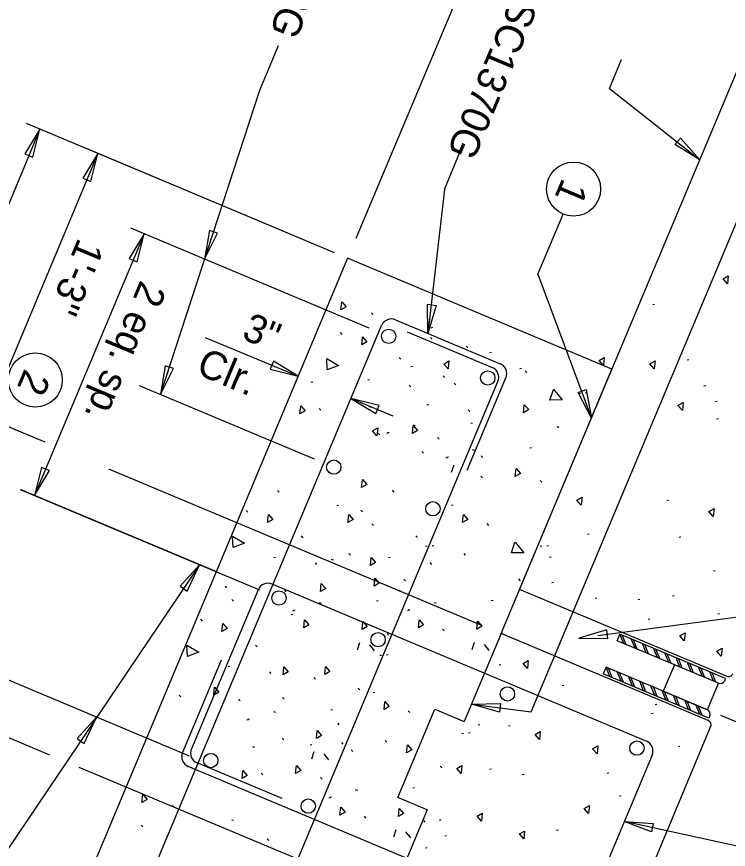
# Model space of a CAD drawing. Extents: x 1968564 to 1968711, y 796599 to 796794.
# Drawn here: x 1968652.64 to 1968665.06, y 796670.24 to 796684.77 of the extents above; entities that cross this region are included whole.
import ezdxf

# ---------------------------------------------------------------- set-up
doc = ezdxf.new("R2010")
doc.units = 0
for name, color, linetype in [('BR_AUTO DIMENSION', 7, 'Continuous'), ('BR_CONCRETE', 7, 'Continuous'), ('BR_DETAILS', 7, 'Continuous'), ('BR_REBAR', 7, 'Continuous'), ('BR_STRUCTURAL STEEL', 7, 'Continuous'), ('BR_TABLE LINES', 7, 'Continuous'), ('BR_TEXT', 7, 'Continuous')]:
    doc.layers.add(name, color=color, linetype=linetype)

msp = doc.modelspace()

# ---------------------------------------------------------------- linework, layer by layer
at = {"layer": 'BR_AUTO DIMENSION'}
for p, q in [((1968664.941, 796696.102), (1968658.562, 796680.894)), ((1968661.621, 796672.639), (1968666.836, 796685.073)), ((1968656.887, 796683.484), (1968657.212, 796684.26)), ((1968662.987, 796683.51), (1968663.2, 796684.017)), ((1968655.153, 796678.177), (1968656.887, 796683.484)), ((1968662.987, 796683.51), (1968664.562, 796682.27)), ((1968657.405, 796680.977), (1968652.818, 796682.901)), ((1968653.049, 796682.804), (1968647.247, 796668.972)), ((1968658.188, 796680.649), (1968653.833, 796682.476)), ((1968654.063, 796682.379), (1968652.129, 796677.768)), ((1968660.108, 796681.751), (1968660.385, 796682.411)), ((1968660.108, 796681.751), (1968659.818, 796679.242)), ((1968661.738, 796680.273), (1968662.179, 796681.323)), ((1968654.869, 796680.979), (1968652.955, 796676.415)), ((1968658.794, 796679.333), (1968654.639, 796681.076)), ((1968661.738, 796680.273), (1968662.672, 796677.764)), ((1968655.936, 796679.172), (1968657.555, 796678.493)), ((1968654.784, 796678.331), (1968657.837, 796677.051)), ((1968659.215, 796677.796), (1968658.477, 796678.106)), ((1968652.903, 796677.443), (1968651.899, 796677.865)), ((1968652.903, 796677.443), (1968651.899, 796677.865)), ((1968652.587, 796677.576), (1968653.134, 796677.347)), ((1968654.248, 796676.88), (1968660.753, 796674.151)), ((1968652.708, 796676.519), (1968656.88, 796674.769)), ((1968656.108, 796675.093), (1968652.725, 796676.512)), ((1968655.837, 796675.204), (1968649.435, 796665.731)), ((1968662.785, 796673.971), (1968666.916, 796674.523)), ((1968655.662, 796671.865), (1968651.507, 796673.607)), ((1968660.58, 796672.776), (1968661.621, 796672.639)), ((1968664.926, 796672.582), (1968671.236, 796669.935)), ((1968652.269, 796672.288), (1968653.22, 796671.889)), ((1968653.729, 796671.675), (1968657.933, 796669.912)), ((1968666.9, 796669.924), (1968663.245, 796670.729))]:
    msp.add_line(p, q, dxfattribs=at)
for points in [[(1968652.925, 796682.314), (1968653.049, 796682.804), (1968652.786, 796682.372)], [(1968664.226, 796682.648), (1968664.562, 796682.27), (1968664.13, 796682.533)], [(1968653.939, 796681.889), (1968654.063, 796682.379), (1968653.801, 796681.947)], [(1968654.745, 796680.489), (1968654.869, 796680.979), (1968654.607, 796680.547)], [(1968656.008, 796681.037), (1968655.924, 796680.538), (1968656.151, 796680.99)], [(1968659.963, 796679.727), (1968659.818, 796679.242), (1968659.815, 796679.748)], [(1968655.237, 796678.676), (1968655.153, 796678.178), (1968655.38, 796678.63)], [(1968657.065, 796678.617), (1968657.555, 796678.493), (1968657.123, 796678.755)], [(1968662.581, 796678.262), (1968662.672, 796677.764), (1968662.439, 796678.213)], [(1968658.968, 796677.982), (1968658.477, 796678.106), (1968658.909, 796677.843)], [(1968653.079, 796676.905), (1968652.955, 796676.415), (1968653.218, 796676.847)], [(1968655.619, 796674.748), (1968655.837, 796675.204), (1968655.495, 796674.832)], [(1968662.94, 796674.069), (1968662.455, 796673.924), (1968662.961, 796673.92)], [(1968661.066, 796672.636), (1968660.58, 796672.776), (1968661.085, 796672.785)], [(1968653.822, 796672.089), (1968654.04, 796672.545), (1968653.698, 796672.173)], [(1968663.718, 796670.548), (1968663.245, 796670.729), (1968663.75, 796670.695)]]:
    msp.add_lwpolyline(points, close=True, dxfattribs=at)
for centre in [(1968662.361, 796681.758), (1968652.969, 796678.429)]:
    msp.add_circle(centre, 0.472, dxfattribs=at)
at = {"layer": 'BR_CONCRETE'}
for p, q in [((1968661.418, 796674.776), (1968665.511, 796684.533)), ((1968658.419, 796680.552), (1968652.617, 796666.719)), ((1968663.03, 796678.618), (1968658.419, 796680.552)), ((1968661.096, 796674.007), (1968663.03, 796678.618)), ((1968665.03, 796673.261), (1968661.418, 796674.776)), ((1968661.096, 796674.007), (1968660.451, 796672.47)), ((1968664.708, 796672.492), (1968661.096, 796674.007)), ((1968664.752, 796672.383), (1968663.068, 796668.368)), ((1968659.807, 796670.933), (1968659.162, 796669.396))]:
    msp.add_line(p, q, dxfattribs=at)
msp.add_lwpolyline([(1968659.807, 796670.933), (1968659.294, 796671.148), (1968659.939, 796672.685), (1968660.451, 796672.47)], dxfattribs=at)
for centre, start, end in [((1968665.062, 796673.338), 247.246, 337.2565), ((1968664.676, 796672.415), 337.246, 67.246)]:
    msp.add_arc(centre, 0.0833, start, end, dxfattribs=at)
at = {"layer": 'BR_DETAILS'}
for p, q in [((1968663.745, 796679.746), (1968663.774, 796679.752)), ((1968658.838, 796679.601), (1968658.866, 796679.571)), ((1968658.291, 796679.254), (1968658.319, 796679.224)), ((1968659.902, 796679.341), (1968659.873, 796679.335)), ((1968659.867, 796679.169), (1968659.896, 796679.139)), ((1968660.486, 796679.019), (1968660.514, 796678.989)), ((1968659.321, 796678.822), (1968659.349, 796678.792)), ((1968660.932, 796678.909), (1968660.902, 796678.903)), ((1968659.52, 796678.664), (1968659.549, 796678.67)), ((1968664.344, 796678.779), (1968664.373, 796678.785)), ((1968661.451, 796678.626), (1968661.421, 796678.621)), ((1968661.516, 796678.587), (1968661.544, 796678.558)), ((1968657.812, 796678.382), (1968657.776, 796678.392)), ((1968658.803, 796678.43), (1968658.773, 796678.424)), ((1968660.084, 796678.502), (1968660.112, 796678.472)), ((1968660.28, 796678.375), (1968660.308, 796678.345)), ((1968659.492, 796678.339), (1968659.52, 796678.309)), ((1968664.636, 796678.328), (1968664.666, 796678.334)), ((1968662.481, 796678.195), (1968662.451, 796678.189)), ((1968662.595, 796678.202), (1968662.565, 796678.196)), ((1968657.922, 796677.933), (1968657.95, 796677.903)), ((1968658.842, 796677.95), (1968658.805, 796677.96)), ((1968659.833, 796677.998), (1968659.803, 796677.992)), ((1968664.835, 796678.051), (1968664.864, 796678.057)), ((1968660.522, 796677.907), (1968660.55, 796677.878)), ((1968659.605, 796677.63), (1968659.569, 796677.64)), ((1968660.596, 796677.678), (1968660.567, 796677.672)), ((1968664.855, 796677.75), (1968664.884, 796677.755)), ((1968658.952, 796677.501), (1968658.98, 796677.471)), ((1968659.131, 796677.502), (1968659.101, 796677.497)), ((1968659.146, 796677.514), (1968659.117, 796677.508)), ((1968662.073, 796677.623), (1968662.101, 796677.593)), ((1968659.986, 796677.428), (1968660.014, 796677.398)), ((1968660.635, 796677.198), (1968660.598, 796677.208)), ((1968661.626, 796677.246), (1968661.596, 796677.24)), ((1968659.715, 796677.181), (1968659.743, 796677.151)), ((1968660.161, 796677.07), (1968660.131, 796677.065)), ((1968660.176, 796677.082), (1968660.146, 796677.076)), ((1968660.75, 796677.108), (1968660.778, 796677.078)), ((1968660.234, 796676.823), (1968660.275, 796676.95)), ((1968660.745, 796676.749), (1968660.773, 796676.719)), ((1968661.779, 796676.676), (1968661.808, 796676.646)), ((1968657.196, 796676.502), (1968657.224, 796676.472)), ((1968659.197, 796676.504), (1968659.225, 796676.474)), ((1968663.99, 796676.326), (1968664.02, 796676.332)), ((1968658.26, 796676.242), (1968658.231, 796676.236)), ((1968660.262, 796676.244), (1968660.232, 796676.239)), ((1968656.649, 796676.155), (1968656.677, 796676.125)), ((1968658.651, 796676.157), (1968658.679, 796676.127)), ((1968658.844, 796675.92), (1968658.872, 796675.891)), ((1968660.846, 796675.923), (1968660.874, 796675.893)), ((1968657.608, 796675.708), (1968657.636, 796675.678)), ((1968659.609, 796675.71), (1968659.638, 796675.68)), ((1968662.607, 796675.737), (1968662.636, 796675.743)), ((1968664.201, 796675.686), (1968664.23, 796675.692)), ((1968659.809, 796675.528), (1968659.779, 796675.522)), ((1968659.923, 796675.535), (1968659.894, 796675.529)), ((1968661.81, 796675.53), (1968661.781, 796675.524)), ((1968661.925, 796675.537), (1968661.895, 796675.532)), ((1968657.161, 796675.331), (1968657.131, 796675.325)), ((1968658.442, 796675.403), (1968658.47, 796675.373)), ((1968659.163, 796675.333), (1968659.133, 796675.327)), ((1968660.444, 796675.405), (1968660.472, 796675.375)), ((1968661.941, 796675.339), (1968661.97, 796675.345)), ((1968657.85, 796675.24), (1968657.878, 796675.211)), ((1968658.171, 796675.285), (1968658.135, 796675.296)), ((1968659.852, 796675.243), (1968659.88, 796675.213)), ((1968664.8, 796675.098), (1968664.829, 796675.104)), ((1968659.401, 796674.956), (1968659.429, 796674.926)), ((1968661.403, 796674.958), (1968661.431, 796674.928)), ((1968661.98, 796674.898), (1968662.009, 796674.903)), ((1968656.28, 796674.834), (1968656.308, 796674.804)), ((1968657.315, 796674.761), (1968657.343, 796674.731)), ((1968659.316, 796674.763), (1968659.344, 796674.733)), ((1968656.398, 796674.6), (1968656.426, 796674.571)), ((1968662.736, 796674.622), (1968662.766, 796674.628)), ((1968663.49, 796674.598), (1968663.519, 796674.603)), ((1968664.085, 796674.661), (1968664.114, 796674.667)), ((1968657.963, 796674.531), (1968657.927, 796674.541)), ((1968658.954, 796674.579), (1968658.925, 796674.573)), ((1968659.964, 796674.533), (1968659.928, 796674.544)), ((1968660.956, 796674.581), (1968660.926, 796674.575)), ((1968657.463, 796674.341), (1968657.433, 796674.335)), ((1968657.489, 796674.403), (1968657.459, 796674.398)), ((1968657.504, 796674.415), (1968657.475, 796674.409)), ((1968659.491, 796674.406), (1968659.461, 796674.4)), ((1968659.506, 796674.417), (1968659.476, 796674.412)), ((1968664.876, 796674.35), (1968664.905, 796674.355)), ((1968655.852, 796674.254), (1968655.88, 796674.224)), ((1968663.662, 796674.255), (1968663.691, 796674.261)), ((1968659.108, 796674.009), (1968659.136, 796673.979)), ((1968660.075, 796674.084), (1968660.103, 796674.054)), ((1968661.109, 796674.011), (1968661.137, 796673.981)), ((1968656.81, 796673.806), (1968656.839, 796673.777)), ((1968658.592, 796673.724), (1968658.633, 796673.851)), ((1968658.799, 796673.811), (1968658.883, 796673.707)), ((1968660.594, 796673.726), (1968660.635, 796673.853)), ((1968660.8, 796673.813), (1968660.885, 796673.71)), ((1968659.011, 796673.626), (1968658.982, 796673.621)), ((1968659.126, 796673.634), (1968659.096, 796673.628)), ((1968656.364, 796673.43), (1968656.334, 796673.424)), ((1968661.063, 796673.461), (1968661.092, 796673.467)), ((1968657.053, 796673.339), (1968657.081, 796673.309)), ((1968657.828, 796673.238), (1968657.856, 796673.208)), ((1968658.604, 796673.054), (1968658.632, 796673.025)), ((1968662.161, 796673.102), (1968662.19, 796673.108)), ((1968655.482, 796672.932), (1968655.511, 796672.903)), ((1968656.517, 796672.86), (1968656.545, 796672.83)), ((1968657.281, 796672.892), (1968657.309, 796672.862)), ((1968658.892, 796672.979), (1968658.863, 796672.973)), ((1968663.784, 796672.767), (1968663.814, 796672.772)), ((1968657.165, 796672.63), (1968657.129, 796672.64)), ((1968658.157, 796672.678), (1968658.127, 796672.672)), ((1968659.476, 796672.657), (1968659.504, 796672.627)), ((1968663.72, 796672.613), (1968663.749, 796672.619)), ((1968656.692, 796672.502), (1968656.662, 796672.496)), ((1968656.707, 796672.514), (1968656.677, 796672.508)), ((1968658.24, 796672.444), (1968658.268, 796672.414)), ((1968660.696, 796672.414), (1968660.726, 796672.42)), ((1968660.441, 796672.264), (1968660.411, 796672.258)), ((1968660.555, 796672.272), (1968660.525, 796672.266)), ((1968661.224, 796672.398), (1968661.254, 796672.404)), ((1968657.276, 796672.18), (1968657.304, 796672.151)), ((1968659.074, 796672.139), (1968659.102, 796672.11)), ((1968656.802, 796672.019), (1968656.766, 796672.03)), ((1968657.793, 796672.067), (1968657.763, 796672.062)), ((1968658.31, 796672.108), (1968658.338, 796672.078)), ((1968658.482, 796671.977), (1968658.51, 796671.947)), ((1968664.189, 796672.035), (1968664.218, 796672.04)), ((1968657.795, 796671.823), (1968657.836, 796671.949)), ((1968658.001, 796671.909), (1968658.086, 796671.806)), ((1968660.033, 796671.692), (1968660.061, 796671.662)), ((1968656.912, 796671.57), (1968656.94, 796671.54)), ((1968660.9, 796671.642), (1968660.929, 796671.648)), ((1968661.467, 796671.546), (1968661.497, 796671.551)), ((1968662.947, 796671.571), (1968662.976, 796671.577)), ((1968657.947, 796671.497), (1968657.975, 796671.468)), ((1968658.595, 796671.267), (1968658.559, 796671.278)), ((1968659.586, 796671.315), (1968659.557, 796671.31)), ((1968658.121, 796671.14), (1968658.091, 796671.134)), ((1968658.136, 796671.152), (1968658.107, 796671.146)), ((1968663.16, 796671.175), (1968663.19, 796671.181)), ((1968655.366, 796671.009), (1968655.394, 796670.979)), ((1968658.705, 796670.818), (1968658.733, 796670.788)), ((1968656.43, 796670.75), (1968656.401, 796670.744)), ((1968659.74, 796670.745), (1968659.768, 796670.716)), ((1968660.022, 796670.754), (1968660.052, 796670.76)), ((1968654.819, 796670.662), (1968654.847, 796670.633)), ((1968659.224, 796670.46), (1968659.265, 796670.587)), ((1968659.431, 796670.547), (1968659.515, 796670.444)), ((1968662.066, 796670.579), (1968662.096, 796670.585)), ((1968657.014, 796670.428), (1968657.042, 796670.398)), ((1968660.117, 796670.479), (1968660.146, 796670.485)), ((1968659.779, 796670.269), (1968659.808, 796670.275))]:
    msp.add_line(p, q, dxfattribs=at)
for points in [[(1968665.048, 796680.108), (1968664.971, 796680.195), (1968665.061, 796680.247), (1968665.048, 796680.108)], [(1968658.316, 796679.789), (1968658.393, 796679.703), (1968658.303, 796679.65), (1968658.316, 796679.789)], [(1968658.678, 796679.181), (1968658.755, 796679.095), (1968658.665, 796679.042), (1968658.678, 796679.181)], [(1968658.055, 796678.804), (1968658.262, 796678.681), (1968658.062, 796678.603), (1968658.055, 796678.799)], [(1968662.882, 796678.684), (1968662.806, 796678.77), (1968662.895, 796678.823), (1968662.882, 796678.684)], [(1968660.172, 796678.621), (1968660.095, 796678.707), (1968660.185, 796678.76), (1968660.172, 796678.621)], [(1968663.769, 796678.624), (1968663.692, 796678.71), (1968663.782, 796678.763), (1968663.769, 796678.624)], [(1968662.01, 796678.267), (1968662.163, 796678.081), (1968661.949, 796678.076), (1968662.009, 796678.263)], [(1968657.6, 796677.977), (1968657.677, 796677.891), (1968657.587, 796677.838), (1968657.6, 796677.977)], [(1968661.501, 796677.997), (1968661.578, 796677.911), (1968661.488, 796677.858), (1968661.501, 796677.997)], [(1968664.26, 796677.895), (1968664.183, 796677.982), (1968664.273, 796678.034), (1968664.26, 796677.895)], [(1968658.931, 796677.456), (1968658.854, 796677.543), (1968658.944, 796677.595), (1968658.931, 796677.456)], [(1968659.564, 796677.637), (1968659.64, 796677.55), (1968659.551, 796677.498), (1968659.564, 796677.637)], [(1968661.357, 796676.885), (1968661.434, 796676.798), (1968661.344, 796676.746), (1968661.357, 796676.885)], [(1968658.676, 796676.692), (1968658.752, 796676.606), (1968658.663, 796676.553), (1968658.676, 796676.692)], [(1968662.496, 796676.248), (1968662.419, 796676.334), (1968662.509, 796676.387), (1968662.496, 796676.248)], [(1968664.799, 796676.047), (1968664.723, 796676.134), (1968664.813, 796676.186), (1968664.799, 796676.047)], [(1968657.036, 796676.082), (1968657.113, 796675.996), (1968657.023, 796675.943), (1968657.036, 796676.082)], [(1968658.438, 796676.082), (1968658.515, 796675.995), (1968658.425, 796675.943), (1968658.438, 796676.082)], [(1968660.439, 796676.084), (1968660.516, 796675.998), (1968660.426, 796675.945), (1968660.439, 796676.084)], [(1968656.413, 796675.705), (1968656.62, 796675.582), (1968656.42, 796675.504), (1968656.413, 796675.701)], [(1968661.34, 796675.602), (1968661.493, 796675.416), (1968661.278, 796675.411), (1968661.339, 796675.598)], [(1968658.829, 796675.33), (1968658.906, 796675.244), (1968658.816, 796675.191), (1968658.829, 796675.33)], [(1968657.96, 796674.881), (1968658.037, 796674.794), (1968657.947, 796674.742), (1968657.96, 796674.881)], [(1968658.894, 796674.972), (1968658.97, 796674.886), (1968658.881, 796674.833), (1968658.894, 796674.972)], [(1968656.239, 796674.181), (1968656.315, 796674.095), (1968656.225, 796674.042), (1968656.239, 796674.181)], [(1968657.667, 796674.243), (1968657.743, 796674.157), (1968657.654, 796674.104), (1968657.667, 796674.243)], [(1968658.685, 796674.218), (1968658.762, 796674.131), (1968658.672, 796674.079), (1968658.685, 796674.218)], [(1968659.668, 796674.245), (1968659.745, 796674.159), (1968659.655, 796674.106), (1968659.668, 796674.245)], [(1968660.687, 796674.22), (1968660.763, 796674.134), (1968660.674, 796674.081), (1968660.687, 796674.22)], [(1968664.292, 796673.878), (1968664.216, 796673.964), (1968664.306, 796674.017), (1968664.292, 796673.878)], [(1968655.616, 796673.803), (1968655.823, 796673.681), (1968655.623, 796673.603), (1968655.616, 796673.799)], [(1968664.939, 796673.612), (1968664.863, 796673.698), (1968664.952, 796673.751), (1968664.939, 796673.612)], [(1968657.306, 796673.427), (1968657.383, 796673.34), (1968657.293, 796673.288), (1968657.306, 796673.427)], [(1968658.032, 796673.429), (1968658.108, 796673.342), (1968658.019, 796673.29), (1968658.032, 796673.429)], [(1968661.558, 796673.399), (1968661.481, 796673.485), (1968661.571, 796673.538), (1968661.558, 796673.399)], [(1968656.095, 796673.068), (1968656.171, 796672.982), (1968656.082, 796672.93), (1968656.095, 796673.068)], [(1968659.07, 796672.818), (1968659.146, 796672.732), (1968659.057, 796672.679), (1968659.07, 796672.818)], [(1968657.888, 796672.316), (1968657.964, 796672.23), (1968657.875, 796672.177), (1968657.888, 796672.316)], [(1968661.766, 796672.157), (1968661.689, 796672.244), (1968661.779, 796672.296), (1968661.766, 796672.157)], [(1968659.461, 796672.067), (1968659.538, 796671.98), (1968659.448, 796671.928), (1968659.461, 796672.067)], [(1968662.77, 796671.908), (1968662.694, 796671.994), (1968662.784, 796672.047), (1968662.77, 796671.908)], [(1968657.524, 796671.706), (1968657.601, 796671.62), (1968657.511, 796671.567), (1968657.524, 796671.706)], [(1968660.4, 796671.564), (1968660.323, 796671.65), (1968660.413, 796671.703), (1968660.4, 796671.564)], [(1968656.59, 796671.615), (1968656.667, 796671.529), (1968656.577, 796671.476), (1968656.59, 796671.615)], [(1968654.844, 796671.198), (1968654.921, 796671.111), (1968654.831, 796671.059), (1968654.844, 796671.198)], [(1968658.299, 796670.98), (1968658.375, 796670.893), (1968658.285, 796670.841), (1968658.299, 796670.98)], [(1968662.624, 796670.866), (1968662.547, 796670.952), (1968662.637, 796671.005), (1968662.624, 796670.866)], [(1968659.317, 796670.954), (1968659.394, 796670.868), (1968659.304, 796670.815), (1968659.317, 796670.954)], [(1968660.755, 796670.732), (1968660.678, 796670.819), (1968660.768, 796670.871), (1968660.755, 796670.732)], [(1968661.491, 796670.424), (1968661.415, 796670.51), (1968661.504, 796670.562), (1968661.491, 796670.424)]]:
    msp.add_lwpolyline(points, dxfattribs=at)
at = {"layer": 'BR_REBAR'}
for p, q in [((1968659.256, 796679.477), (1968661.081, 796678.712)), ((1968653.87, 796667.12), (1968659.011, 796679.377)), ((1968659.458, 796679.269), (1968659.92, 796679.075)), ((1968659.92, 796679.075), (1968660.941, 796678.647)), ((1968655.945, 796666.25), (1968661.041, 796678.401)), ((1968660.506, 796676.857), (1968661.182, 796678.466)), ((1968656.856, 796674.769), (1968655.693, 796671.995)), ((1968663.63, 796672.131), (1968657.101, 796674.869)), ((1968656.214, 796673.542), (1968655.539, 796671.932)), ((1968663.731, 796671.886), (1968662.522, 796669.004)), ((1968662.277, 796668.903), (1968655.636, 796671.689)), ((1968657.276, 796671.128), (1968655.793, 796671.75))]:
    msp.add_line(p, q, dxfattribs=at)
for centre in [(1968659.135, 796679.19), (1968660.864, 796678.464), (1968658.178, 796676.908), (1968659.907, 796676.182), (1968657.221, 796674.626), (1968658.95, 796673.9), (1968661.208, 796672.953), (1968663.466, 796672.007), (1968656.032, 796671.791), (1968657.732, 796670.996)]:
    msp.add_circle(centre, 0.125, dxfattribs=at)
for centre, start, end in [((1968659.184, 796679.305), 67.246, 157.246), ((1968661.009, 796678.539), 337.246, 67.246), ((1968660.868, 796678.474), 337.246, 67.246), ((1968657.029, 796674.696), 67.246, 157.246), ((1968663.558, 796671.958), 337.246, 67.246), ((1968655.865, 796671.923), 157.246, 247.246), ((1968655.712, 796671.86), 157.246, 247.246)]:
    msp.add_arc(centre, 0.188, start, end, dxfattribs=at)
at = {"layer": 'BR_STRUCTURAL STEEL'}
for p, q in [((1968663.237, 796673.832), (1968663.17, 796673.996)), ((1968663.277, 796673.815), (1968663.21, 796673.979)), ((1968663.433, 796673.75), (1968663.366, 796673.914)), ((1968663.473, 796673.733), (1968663.406, 796673.897)), ((1968663.629, 796673.668), (1968663.562, 796673.831)), ((1968663.669, 796673.651), (1968663.603, 796673.814)), ((1968663.825, 796673.586), (1968663.758, 796673.749)), ((1968663.865, 796673.569), (1968663.799, 796673.732)), ((1968664.021, 796673.503), (1968663.954, 796673.667)), ((1968664.061, 796673.486), (1968663.995, 796673.65)), ((1968664.217, 796673.421), (1968664.15, 796673.585)), ((1968664.258, 796673.404), (1968664.191, 796673.568)), ((1968664.413, 796673.339), (1968664.346, 796673.503)), ((1968664.454, 796673.322), (1968664.387, 796673.486)), ((1968662.995, 796673.256), (1968662.928, 796673.42)), ((1968663.036, 796673.239), (1968662.969, 796673.402)), ((1968663.191, 796673.174), (1968663.124, 796673.337)), ((1968663.232, 796673.157), (1968663.165, 796673.32)), ((1968664.609, 796673.257), (1968664.542, 796673.42)), ((1968664.65, 796673.24), (1968664.583, 796673.403)), ((1968664.805, 796673.175), (1968664.738, 796673.338)), ((1968664.846, 796673.157), (1968664.779, 796673.321)), ((1968663.387, 796673.092), (1968663.32, 796673.255)), ((1968663.428, 796673.074), (1968663.361, 796673.238)), ((1968663.583, 796673.009), (1968663.516, 796673.173)), ((1968663.624, 796672.992), (1968663.557, 796673.156)), ((1968663.779, 796672.927), (1968663.712, 796673.091)), ((1968663.82, 796672.91), (1968663.753, 796673.074)), ((1968663.975, 796672.845), (1968663.908, 796673.008)), ((1968664.016, 796672.828), (1968663.949, 796672.991)), ((1968664.171, 796672.763), (1968664.104, 796672.926)), ((1968664.212, 796672.746), (1968664.145, 796672.909)), ((1968664.367, 796672.68), (1968664.3, 796672.844)), ((1968664.408, 796672.663), (1968664.341, 796672.827)), ((1968664.563, 796672.598), (1968664.496, 796672.762)), ((1968664.604, 796672.581), (1968664.537, 796672.745))]:
    msp.add_line(p, q, dxfattribs=at)
for points in [[(1968664.889, 796673.139), (1968663.121, 796673.881), (1968663.17, 796673.996)], [(1968664.998, 796673.184), (1968665.014, 796673.222), (1968663.17, 796673.996)], [(1968664.695, 796672.678), (1968662.928, 796673.42), (1968662.88, 796673.304)], [(1968664.74, 796672.569), (1968664.724, 796672.531), (1968662.88, 796673.304)]]:
    msp.add_lwpolyline(points, dxfattribs=at)
for centre, start, end in [((1968664.921, 796673.216), 247.246, 337.246), ((1968664.663, 796672.601), 337.246, 67.246)]:
    msp.add_arc(centre, 0.0833, start, end, dxfattribs=at)
at = {"layer": 'BR_TABLE LINES'}
msp.add_lwpolyline([(1968664.695, 796672.678), (1968664.889, 796673.139), (1968664.12, 796673.462), (1968663.927, 796673.001)], close=True, dxfattribs=at)

# ---------------------------------------------------------------- texts
at = {"layer": 'BR_AUTO DIMENSION'}
for s, rotation, p in [('1\'-3"', 247.246, (1968653.724, 796680.924)), ('2 eq. sp.', 247.246, (1968654.808, 796680.186)), ('3"', 337.246, (1968656.55, 796679.156))]:
    msp.add_text(s, height=0.5, rotation=rotation, dxfattribs=at).set_placement(p)
at = {"layer": 'BR_TEXT'}
for s, height, rotation, p in [('2-A1970G', 0.4999, 247.246, (1968658.227, 796687.329)), ('SC1370G', 0.4999, 247.246, (1968661.283, 796685.119)), ('1', 0.5, 247.246, (1968662.169, 796681.967)), ('Clr.', 0.5, 337.246, (1968655.753, 796678.543)), ('2', 0.5, 247.246, (1968652.787, 796678.642))]:
    msp.add_text(s, height=height, rotation=rotation, dxfattribs=at).set_placement(p)

doc.saveas('drawing.dxf')
